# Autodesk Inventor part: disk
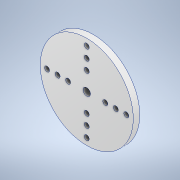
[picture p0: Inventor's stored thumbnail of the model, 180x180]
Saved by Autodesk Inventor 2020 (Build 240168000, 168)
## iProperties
Created: 2023-02
Part Number: disk
Material: Aluminium 6061
Document SubType Name: Modeling
Designer: Admin
Density: 2.7 g/cm^3
Appearance: Aluminium — płaski
Author: Admin
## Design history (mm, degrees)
sketch "Szkic1"
  geometry: C1 r 75 at (0, 0); C2 r 6 at (0, 0); 1 further point
  constraints: 2 centre point, 2 coincident
  dimensions: "d0" = 150 diameter of C1; "d1" = 12 diameter of C2
extrude "Wyciągnięcie proste1" new body sketch "Szkic1" distance "d2" = 10.5; taper "d3" = 0 deg
sketch "Szkic2"
  geometry: L1 (0, 0)-(0, 47); L2 (0, 0)-(0, 30); L3 (0, 0)-(0, 64); C1 r 4 at (0, 47); C2 r 4 at (0, 30); C3 r 4 at (0, 64)
  constraints: 6 end point, 3 centre point, 3 coincident, 2 point on line, 1 vertical
  dimensions: "d4" = 47 distance of L1.start L1.end; "d5" = 8 diameter of C1; "d6" = 30 distance of L1.start L2.end; "d7" = 8 diameter of C2; "d8" = 64 distance of L1.start L3.end; "d9" = 8 diameter of C3
extrude "Wyciągnięcie proste2" cut sketch "Szkic2" distance "d10" = 10.5; taper "d11" = 0 deg
pattern_circular "Szyk kołowy1" dims angle "d13" = 360 deg
node "Bryła1"
